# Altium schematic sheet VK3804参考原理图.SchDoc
size A4
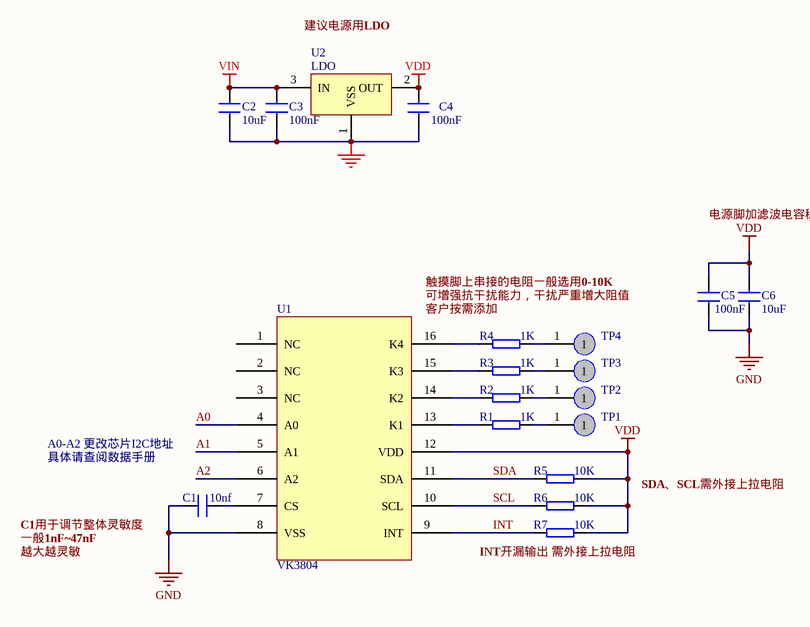
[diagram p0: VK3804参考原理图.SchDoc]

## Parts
C1  value 10nf  [0603-C]  (hidden comment: CAP)
C2  10uF  [0805-C]
C3  100nF  [0805-C]
C4  100nF  [0805-C]
C5  100nF  [0603-C]
C6  10uF  [0603-C]
R1  1K  [0603-R]
R2  1K  [0603-R]
R3  1K  [0603-R]
R4  1K  [0603-R]
R5  10K  [0603-R]
R6  10K  [0603-R]
R7  10K  [0603-R]
TP1  TPAD  [TP-PAD0]  (value not drawn)
TP2  TPAD  [TP-PAD0]  (value not drawn)
TP3  TPAD  [TP-PAD0]  (value not drawn)
TP4  TPAD  [TP-PAD0]  (value not drawn)
U1  VK3804  [SO-16]
U2  LDO  [SOT-23]

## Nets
GND: C1.1 C2.2 C3.2 C4.2 C5.2 C6.2 U1.8(VSS) U2.1(VSS)
VDD: C4.1 C5.1 C6.1 R5.2 R6.2 R7.2 U1.12(VDD) U2.2(OUT)
VIN: C2.1 C3.1 U2.3(IN)
A0: U1.4(A0)
A1: U1.5(A1)
A2: U1.6(A2)
INT: R7.1 U1.9(INT)
SCL: R6.1 U1.10(SCL)
SDA: R5.1 U1.11(SDA)
NetC1_2: C1.2 U1.7(CS)
NetR1_1: R1.1 U1.13(K1)
NetR1_2: R1.2 TP1.1
NetR2_1: R2.1 U1.14(K2)
NetR2_2: R2.2 TP2.1
NetR3_1: R3.1 U1.15(K3)
NetR3_2: R3.2 TP3.1
NetR4_1: R4.1 U1.16(K4)
NetR4_2: R4.2 TP4.1

Not connected (* = marked no-connect by the designer): U1 1(NC) 2(NC) 3(NC)

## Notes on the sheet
- 建议电源用LDO
- 电源脚加滤波电容稳定电源
- 触摸脚上串接的电阻一般选用0-10K
- 可增强抗干扰能力，干扰严重增大阻值
- 客户按需添加
- A0-A2 更改芯片I2C地址
- 具体请查阅数据手册
- C1用于调节整体灵敏度
- SDA、SCL需外接上拉电阻
- 一般1nF~47nF
- 越大越灵敏
- (near R7) INT开漏输出 需外接上拉电阻

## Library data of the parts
C1-C6 = CAP: Capacitor
R1-R4 = RES: Resistor
R5-R7 = RES1: Resistor
TP1-TP4 = TPAD: TESTING
U2 = V6206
